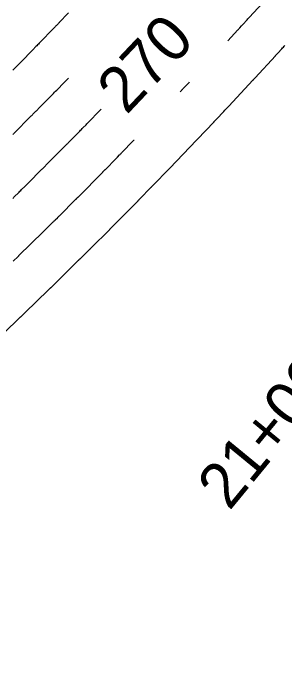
# Model space of a CAD drawing. Extents: x 1710723 to 1713003, y 548603 to 551142.
# Drawn here: x 1712212.6 to 1712248.3, y 549302.6 to 549389.7 of the extents above; entities that cross this region are included whole.
import ezdxf

# ---------------------------------------------------------------- set-up
doc = ezdxf.new("R2010")
doc.units = 0
for name, color, linetype in [('R_Contour Annot', 7, 'Continuous'), ('R_Contours', 7, 'Continuous'), ('R_Horz Alg', 7, 'Continuous'), ('R_Horz Alg Annot', 7, 'Continuous')]:
    doc.layers.add(name, color=color, linetype=linetype)

msp = doc.modelspace()

# ---------------------------------------------------------------- linework, layer by layer
at = {"layer": 'R_Contours'}
for points in [[(1712240.826, 549386.134), (1712242.133, 549387.557), (1712242.195, 549387.624), (1712242.257, 549387.691), (1712242.319, 549387.757), (1712242.381, 549387.824), (1712242.629, 549388.089), (1712242.691, 549388.156), (1712242.752, 549388.222), (1712242.814, 549388.289), (1712242.875, 549388.356), (1712243.283, 549388.804), (1712243.372, 549388.901), (1712243.46, 549388.998), (1712243.548, 549389.095), (1712243.636, 549389.192), (1712246.545, 549392.411)], [(1712219.832, 549389.812), (1712219.663, 549389.634), (1712218.719, 549388.638), (1712218.654, 549388.569), (1712218.588, 549388.501), (1712218.522, 549388.432), (1712218.457, 549388.364), (1712218.192, 549388.092), (1712218.126, 549388.024), (1712218.061, 549387.956), (1712217.995, 549387.888), (1712217.929, 549387.82), (1712215.979, 549385.785), (1712215.873, 549385.675), (1712215.767, 549385.565), (1712215.66, 549385.455), (1712215.554, 549385.346), (1712215.126, 549384.909), (1712215.02, 549384.8), (1712214.913, 549384.691), (1712214.806, 549384.581), (1712214.7, 549384.472), (1712213.976, 549383.724), (1712213.819, 549383.564), (1712213.663, 549383.403), (1712213.505, 549383.243), (1712213.348, 549383.083), (1712212.517, 549382.243)], [(1712209.633, 549346.039), (1712213.257, 549349.502), (1712213.286, 549349.529), (1712213.314, 549349.557), (1712213.343, 549349.584), (1712213.372, 549349.611), (1712213.488, 549349.72), (1712213.517, 549349.748), (1712213.546, 549349.775), (1712213.575, 549349.803), (1712213.603, 549349.83), (1712213.906, 549350.123), (1712213.967, 549350.18), (1712214.027, 549350.238), (1712214.087, 549350.296), (1712214.146, 549350.355), (1712217.156, 549353.275), (1712217.188, 549353.307), (1712217.22, 549353.338), (1712217.253, 549353.369), (1712217.285, 549353.4), (1712217.461, 549353.568), (1712217.489, 549353.595), (1712217.536, 549353.64), (1712217.555, 549353.658), (1712217.573, 549353.677), (1712221.169, 549357.214), (1712221.191, 549357.236), (1712221.213, 549357.258), (1712221.235, 549357.28), (1712221.258, 549357.301), (1712221.347, 549357.388), (1712221.369, 549357.41), (1712221.392, 549357.432), (1712221.414, 549357.454), (1712221.436, 549357.475), (1712222.399, 549358.432), (1712222.43, 549358.463), (1712222.461, 549358.493), (1712222.492, 549358.524), (1712222.523, 549358.554), (1712222.647, 549358.676), (1712222.678, 549358.707), (1712222.709, 549358.737), (1712222.739, 549358.768), (1712222.77, 549358.798), (1712225.256, 549361.286), (1712225.284, 549361.314), (1712225.312, 549361.342), (1712225.368, 549361.397), (1712225.382, 549361.411), (1712225.396, 549361.425), (1712225.41, 549361.439), (1712225.424, 549361.453), (1712228.984, 549365.06), (1712229.017, 549365.093), (1712229.05, 549365.127), (1712229.116, 549365.193), (1712229.133, 549365.21), (1712229.15, 549365.226), (1712229.166, 549365.243), (1712229.183, 549365.26), (1712230.732, 549366.846), (1712230.761, 549366.877), (1712230.791, 549366.907), (1712230.821, 549366.937), (1712230.851, 549366.968), (1712230.971, 549367.089), (1712231, 549367.119), (1712231.03, 549367.149), (1712231.06, 549367.18), (1712231.09, 549367.21), (1712232.955, 549369.135), (1712232.991, 549369.172), (1712233.027, 549369.209), (1712233.1, 549369.283), (1712233.118, 549369.301), (1712233.136, 549369.32), (1712233.154, 549369.338), (1712233.172, 549369.357), (1712236.699, 549373.037), (1712236.721, 549373.06), (1712236.743, 549373.083), (1712236.788, 549373.129), (1712236.81, 549373.152), (1712236.833, 549373.175), (1712238.956, 549375.417), (1712238.985, 549375.447), (1712239.014, 549375.478), (1712239.042, 549375.508), (1712239.071, 549375.538), (1712239.187, 549375.659), (1712239.216, 549375.689), (1712239.245, 549375.719), (1712239.274, 549375.75), (1712239.303, 549375.78), (1712240.267, 549376.805), (1712240.437, 549376.986), (1712240.607, 549377.168), (1712240.776, 549377.349), (1712240.946, 549377.531), (1712244.104, 549380.925), (1712244.126, 549380.948), (1712244.148, 549380.972), (1712244.171, 549380.996), (1712244.193, 549381.019), (1712244.32, 549381.153), (1712244.339, 549381.173), (1712244.37, 549381.206), (1712244.389, 549381.226), (1712247.069, 549384.143), (1712247.096, 549384.173), (1712247.124, 549384.203), (1712247.151, 549384.233), (1712247.179, 549384.263), (1712247.29, 549384.382), (1712247.318, 549384.411), (1712247.346, 549384.441), (1712247.373, 549384.471), (1712247.401, 549384.501), (1712247.927, 549385.078), (1712248.024, 549385.184), (1712248.121, 549385.291), (1712248.217, 549385.397), (1712248.314, 549385.504)], [(1712212.526, 549373.786), (1712212.59, 549373.851), (1712214.927, 549376.219), (1712215.004, 549376.296), (1712215.081, 549376.374), (1712215.158, 549376.451), (1712215.235, 549376.529), (1712215.545, 549376.838), (1712215.622, 549376.916), (1712215.699, 549376.993), (1712215.775, 549377.071), (1712215.852, 549377.149), (1712216.612, 549377.927), (1712216.751, 549378.069), (1712216.89, 549378.211), (1712217.029, 549378.352), (1712217.168, 549378.493), (1712217.726, 549379.057), (1712217.866, 549379.198), (1712218.005, 549379.34), (1712218.143, 549379.482), (1712218.281, 549379.624), (1712219.264, 549380.637), (1712219.348, 549380.724), (1712219.433, 549380.811), (1712219.517, 549380.898), (1712219.602, 549380.984), (1712219.823, 549381.211)], [(1712234.533, 549379.389), (1712234.647, 549379.508), (1712234.711, 549379.575), (1712234.775, 549379.642), (1712234.839, 549379.709), (1712234.903, 549379.777), (1712235.706, 549380.631), (1712235.778, 549380.708)], [(1712212.496, 549365.37), (1712212.572, 549365.444), (1712212.648, 549365.52), (1712212.724, 549365.595), (1712213.229, 549366.096), (1712213.335, 549366.202), (1712213.441, 549366.306), (1712213.548, 549366.411), (1712213.654, 549366.516), (1712214.08, 549366.934), (1712214.186, 549367.039), (1712214.292, 549367.144), (1712214.398, 549367.249), (1712214.503, 549367.354), (1712216.295, 549369.147), (1712216.343, 549369.194), (1712216.39, 549369.242), (1712216.438, 549369.29), (1712216.486, 549369.337), (1712216.678, 549369.527), (1712216.725, 549369.575), (1712216.773, 549369.623), (1712216.821, 549369.671), (1712216.868, 549369.718), (1712219.612, 549372.499), (1712219.669, 549372.556), (1712219.726, 549372.614), (1712219.783, 549372.671), (1712219.84, 549372.728), (1712220.068, 549372.956), (1712220.125, 549373.014), (1712220.182, 549373.071), (1712220.239, 549373.128), (1712220.296, 549373.186), (1712221.318, 549374.234), (1712221.421, 549374.338), (1712221.523, 549374.443), (1712221.626, 549374.547), (1712221.729, 549374.651), (1712222.141, 549375.068), (1712222.244, 549375.172), (1712222.346, 549375.276), (1712222.449, 549375.381), (1712222.551, 549375.486), (1712223.828, 549376.803), (1712223.89, 549376.867), (1712223.952, 549376.931), (1712224.014, 549376.995), (1712224.077, 549377.059), (1712224.145, 549377.129)], [(1712212.534, 549357.085), (1712212.605, 549357.154), (1712212.677, 549357.223), (1712213.066, 549357.594), (1712213.108, 549357.634), (1712213.149, 549357.674), (1712213.231, 549357.753), (1712213.252, 549357.773), (1712213.273, 549357.793), (1712213.293, 549357.813), (1712213.314, 549357.833), (1712216.487, 549360.956), (1712216.536, 549361.004), (1712216.586, 549361.053), (1712216.635, 549361.101), (1712216.685, 549361.149), (1712216.883, 549361.342), (1712216.933, 549361.39), (1712216.982, 549361.438), (1712217.031, 549361.487), (1712217.08, 549361.535), (1712217.814, 549362.264), (1712217.883, 549362.332), (1712217.951, 549362.4), (1712218.02, 549362.467), (1712218.088, 549362.535), (1712218.363, 549362.805), (1712218.432, 549362.873), (1712218.5, 549362.94), (1712218.569, 549363.008), (1712218.637, 549363.076), (1712220.775, 549365.216), (1712220.806, 549365.247), (1712220.837, 549365.278), (1712220.868, 549365.309), (1712220.899, 549365.339), (1712221.023, 549365.462), (1712221.054, 549365.493), (1712221.085, 549365.524), (1712221.115, 549365.555), (1712221.146, 549365.586), (1712224.298, 549368.779), (1712224.335, 549368.817), (1712224.371, 549368.854), (1712224.408, 549368.89), (1712224.445, 549368.927), (1712224.592, 549369.075), (1712224.629, 549369.112), (1712224.666, 549369.149), (1712224.703, 549369.186), (1712224.739, 549369.223), (1712226.025, 549370.54), (1712226.091, 549370.608), (1712226.157, 549370.675), (1712226.224, 549370.742), (1712226.29, 549370.809), (1712226.556, 549371.078), (1712226.622, 549371.145), (1712226.688, 549371.213), (1712226.754, 549371.28), (1712226.82, 549371.348), (1712228.391, 549372.969), (1712228.431, 549373.01), (1712228.468, 549373.047)]]:
    msp.add_lwpolyline(points, dxfattribs=at)
at = {"layer": 'R_Horz Alg'}
for centre, radius, start, end in [((1711727.021, 549745.305), 532.984, 270.64281, 347.20664), ((1711777.174, 549719.88), 636.62, 271.078651, 340.773399)]:
    msp.add_arc(centre, radius, start, end, dxfattribs=at)

# ---------------------------------------------------------------- texts
at = {"layer": 'R_Contour Annot'}
msp.add_text('270', height=6, rotation=46.63846, dxfattribs=at).set_placement((1712227.462, 549376.271))
at = {"layer": 'R_Horz Alg Annot'}
msp.add_text('21+00', height=6, rotation=50.60881, dxfattribs=at).set_placement((1712241.006, 549324.117))

doc.saveas('drawing.dxf')
